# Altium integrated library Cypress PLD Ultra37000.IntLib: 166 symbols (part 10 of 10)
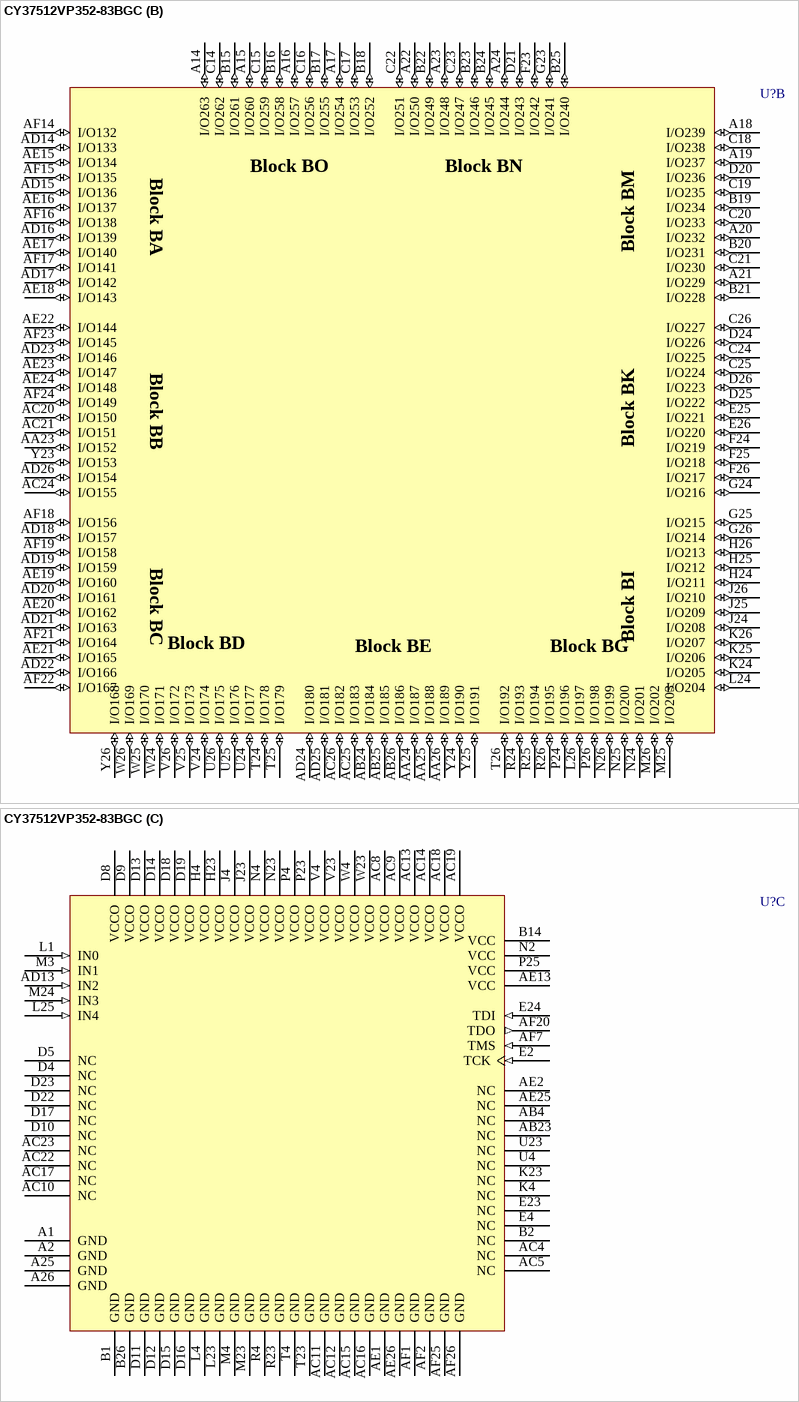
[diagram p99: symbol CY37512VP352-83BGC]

## CY37512VP352-83BGC
designator U?
Ultra37000 3.3V, ISR High-Performance CPLD
footprint BG352 (BGA, 388-Leads, Body 35x35mm, Pitch 1.27mm)
3D model CY37512VP352-BG352 (388-Ball Ball Grid Array 1.27 mm Pitch)
part A pins: A3 I/O19 (io), A4 I/O15 (io), A5 I/O13 (io), A6 I/O34 (io), A7 I/O31 (io), A8 I/O28 (io), A9 I/O25 (io), A10 I/O10 (io), A11 I/O7 (io), A12 I/O4 (io), A13 I/O1 (io), AA1 I/O74 (io), AA2 I/O75 (io), AA3 I/O76 (io), AA4 I/O111 (io), AB1 I/O77 (io), AB2 I/O78 (io), AB3 I/O79 (io), AC1 I/O81 (io), AC2 I/O80 (io), AC3 I/O108 (io), AC6 I/O112 (io), AC7 I/O113 (io), AD1 I/O109 (io), AD2 I/O82 (io), AD3 I/O83 (io), AD4 I/O117 (io), AD5 I/O97 (io), AD6 I/O100 (io), AD7 I/O102 (io), AD8 I/O105 (io), AD9 I/O120 (io), AD10 I/O123 (io), AD11 I/O126 (io), AD12 I/O129 (io), AE3 I/O115 (io), AE4 I/O116 (io), AE5 I/O119 (io), AE6 I/O98 (io), AE7 I/O101 (io), AE8 I/O103 (io), AE9 I/O106 (io), AE10 I/O121 (io), AE11 I/O124 (io), AE12 I/O127 (io), AE14 I/O130 (io), AF3 I/O114 (io), AF4 I/O118 (io), AF5 I/O96 (io), AF6 I/O99 (io), AF8 I/O104 (io), AF9 I/O107 (io), AF10 I/O122 (io), AF11 I/O125 (io), AF12 I/O128 (io), AF13 I/O131 (io), B3 I/O18 (io), B4 I/O17 (io), B5 I/O14 (io), B6 I/O35 (io), B7 I/O32 (io), B8 I/O29 (io), B9 I/O26 (io), B10 I/O11 (io), B11 I/O8 (io), B12 I/O5 (io), B13 I/O2 (io), C1 I/O23 (io), C2 I/O38 (io), C3 I/O37 (io), C4 I/O16 (io), C5 I/O12 (io), C6 I/O33 (io), C7 I/O30 (io), C8 I/O27 (io), C9 I/O24 (io), C10 I/O9 (io), C11 I/O6 (io), C12 I/O3 (io), C13 I/O0 (io), D1 I/O39 (io), D2 I/O40 (io), D3 I/O36 (io), D6 I/O21 (io), D7 I/O20 (io), E1 I/O42 (io), E3 I/O41 (io), F1 I/O45 (io), F2 I/O44 (io), F3 I/O43 (io), F4 I/O22 (io), G1 I/O48 (io), G2 I/O47 (io), G3 I/O46 (io), G4 I/O63 (io), H1 I/O49 (io), H2 I/O50 (io), H3 I/O51 (io), J1 I/O52 (io), J2 I/O53 (io), J3 I/O54 (io), K1 I/O55 (io), K2 I/O56 (io), K3 I/O57 (io), L2 I/O59 (io), L3 I/O58 (io), M1 I/O61 (io), M2 I/O60 (io), N1 I/O64 (io), N3 I/O62 (io), P1 I/O65 (io), P2 I/O66 (io), P3 I/O67 (io), R1 I/O68 (io), R2 I/O69 (io), R3 I/O70 (io), T1 I/O71 (io), T2 I/O84 (io), T3 I/O85 (io), U1 I/O88 (io), U2 I/O87 (io), U3 I/O86 (io), V1 I/O91 (io), V2 I/O90 (io), V3 I/O89 (io), W1 I/O94 (io), W2 I/O93 (io), W3 I/O92 (io), Y1 I/O95 (io), Y2 I/O72 (io), Y3 I/O73 (io), Y4 I/O110 (io)
part B pins: A14 I/O263 (io), A15 I/O260 (io), A16 I/O257 (io), A17 I/O254 (io), A18 I/O239 (io), A19 I/O237 (io), A20 I/O232 (io), A21 I/O229 (io), A22 I/O250 (io), A23 I/O248 (io), A24 I/O244 (io), AA23 I/O152 (io), AA24 I/O187 (io), AA25 I/O188 (io), AA26 I/O189 (io), AB24 I/O184 (io), AB25 I/O185 (io), AB26 I/O186 (io), AC20 I/O150 (io), AC21 I/O151 (io), AC24 I/O155 (io), AC25 I/O183 (io), AC26 I/O182 (io), AD14 I/O133 (io), AD15 I/O136 (io), AD16 I/O139 (io), AD17 I/O142 (io), AD18 I/O157 (io), AD19 I/O159 (io), AD20 I/O161 (io), AD21 I/O163 (io), AD22 I/O166 (io), AD23 I/O146 (io), AD24 I/O180 (io), AD25 I/O181 (io), AD26 I/O154 (io), AE15 I/O134 (io), AE16 I/O137 (io), AE17 I/O140 (io), AE18 I/O143 (io), AE19 I/O160 (io), AE20 I/O162 (io), AE21 I/O165 (io), AE22 I/O144 (io), AE23 I/O147 (io), AE24 I/O148 (io), AF14 I/O132 (io), AF15 I/O135 (io), AF16 I/O138 (io), AF17 I/O141 (io), AF18 I/O156 (io), AF19 I/O158 (io), AF21 I/O164 (io), AF22 I/O167 (io), AF23 I/O145 (io), AF24 I/O149 (io), B15 I/O261 (io), B16 I/O258 (io), B17 I/O255 (io), B18 I/O252 (io), B19 I/O234 (io), B20 I/O231 (io), B21 I/O228 (io), B22 I/O249 (io), B23 I/O246 (io), B24 I/O245 (io), B25 I/O240 (io), C14 I/O262 (io), C15 I/O259 (io), C16 I/O256 (io), C17 I/O253 (io), C18 I/O238 (io), C19 I/O235 (io), C20 I/O233 (io), C21 I/O230 (io), C22 I/O251 (io), C23 I/O247 (io), C24 I/O225 (io), C25 I/O224 (io), C26 I/O227 (io), D20 I/O236 (io), D21 I/O243 (io), D24 I/O226 (io), D25 I/O222 (io), D26 I/O223 (io), E25 I/O221 (io), E26 I/O220 (io), F23 I/O242 (io), F24 I/O219 (io), F25 I/O218 (io), F26 I/O217 (io), G23 I/O241 (io), G24 I/O216 (io), G25 I/O215 (io), G26 I/O214 (io), H24 I/O211 (io), H25 I/O212 (io), H26 I/O213 (io), J24 I/O208 (io), J25 I/O209 (io), J26 I/O210 (io), K24 I/O205 (io), K25 I/O206 (io), K26 I/O207 (io), L24 I/O204 (io), L26 I/O197 (io), M25 I/O203 (io), M26 I/O202 (io), N24 I/O201 (io), N25 I/O200 (io), N26 I/O199 (io), P24 I/O196 (io), P26 I/O198 (io), R24 I/O193 (io), R25 I/O194 (io), R26 I/O195 (io), T24 I/O178 (io), T25 I/O179 (io), T26 I/O192 (io), U24 I/O177 (io), U25 I/O176 (io), U26 I/O175 (io), V24 I/O174 (io), V25 I/O173 (io), V26 I/O172 (io), W24 I/O171 (io), W25 I/O170 (io), W26 I/O169 (io), Y23 I/O153 (io), Y24 I/O190 (io), Y25 I/O191 (io), Y26 I/O168 (io)
part C pins: A1 GND (power), A2 GND (power), A25 GND (power), A26 GND (power), AB4 NC, AB23 NC, AC4 NC, AC5 NC, AC8 VCCO (power), AC9 VCCO (power), AC10 NC, AC11 GND (power), AC12 GND (power), AC13 VCCO (power), AC14 VCCO (power), AC15 GND (power), AC16 GND (power), AC17 NC, AC18 VCCO (power), AC19 VCCO (power), AC22 NC, AC23 NC, AD13 IN2 (in), AE1 GND (power), AE2 NC, AE13 VCC (power), AE25 NC, AE26 GND (power), AF1 GND (power), AF2 GND (power), AF7 TMS (in), AF20 TDO (out), AF25 GND (power), AF26 GND (power), B1 GND (power), B2 NC, B14 VCC (power), B26 GND (power), D4 NC, D5 NC, D8 VCCO (power), D9 VCCO (power), D10 NC, D11 GND (power), D12 GND (power), D13 VCCO (power), D14 VCCO (power), D15 GND (power), D16 GND (power), D17 NC, D18 VCCO (power), D19 VCCO (power), D22 NC, D23 NC, E2 TCK (in), E4 NC, E23 NC, E24 TDI (in), H4 VCCO (power), H23 VCCO (power), J4 VCCO (power), J23 VCCO (power), K4 NC, K23 NC, L1 IN0 (in), L4 GND (power), L23 GND (power), L25 IN4 (in), M3 IN1 (in), M4 GND (power), M23 GND (power), M24 IN3 (in), N2 VCC (power), N4 VCCO (power), N23 VCCO (power), P4 VCCO (power), P23 VCCO (power), P25 VCC (power), R4 GND (power), R23 GND (power), T4 GND (power), T23 GND (power), U4 NC, U23 NC, V4 VCCO (power), V23 VCCO (power), W4 VCCO (power), W23 VCCO (power)

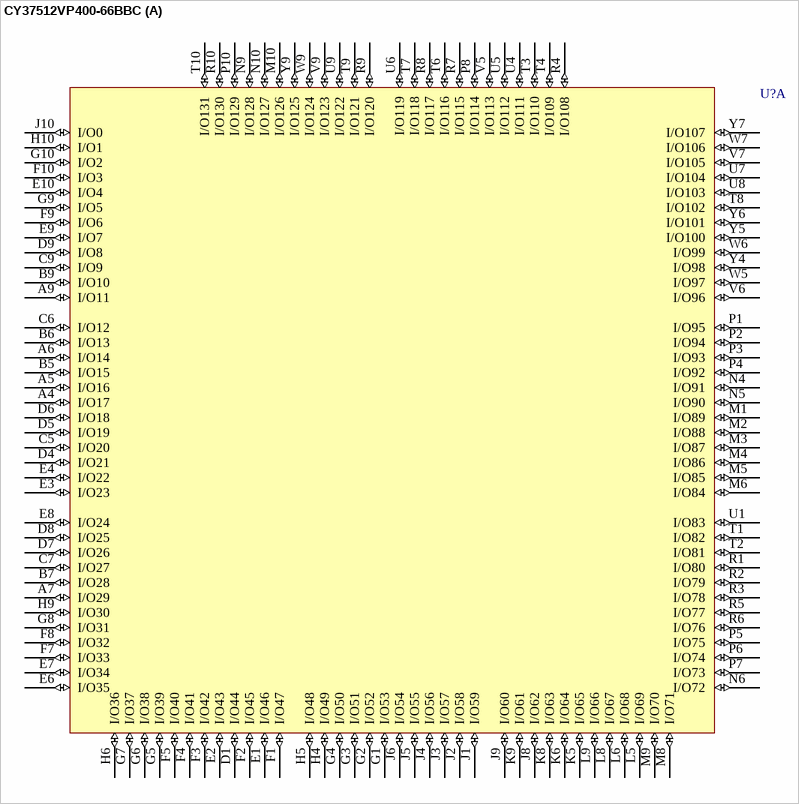
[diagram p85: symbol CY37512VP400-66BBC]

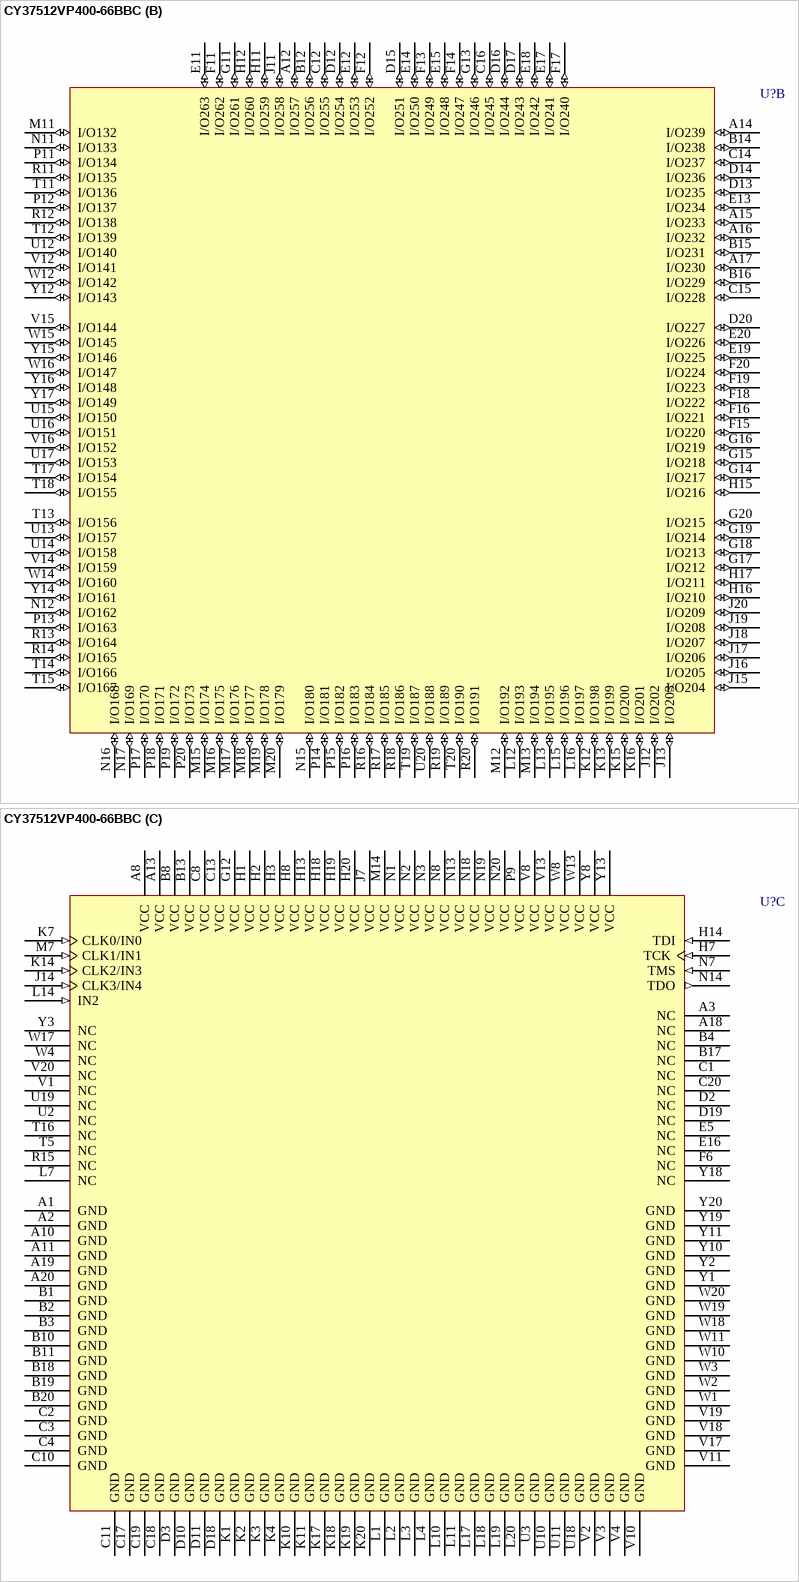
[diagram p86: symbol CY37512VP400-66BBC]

## CY37512VP400-66BBC
designator U?
Ultra37000 3.3V, ISR High-Performance CPLD
footprint BB400 (BGA, 400-Leads, Body 21x21mm, Pitch 1mm)
3D model CY37512VP400-BB400 (400-Ball Fine Pitch Ball Grid Array 1 mm Pitch)
part A pins: A4 I/O17 (io), A5 I/O16 (io), A6 I/O14 (io), A7 I/O29 (io), A9 I/O11 (io), B5 I/O15 (io), B6 I/O13 (io), B7 I/O28 (io), B9 I/O10 (io), C5 I/O20 (io), C6 I/O12 (io), C7 I/O27 (io), C9 I/O9 (io), D1 I/O44 (io), D4 I/O21 (io), D5 I/O19 (io), D6 I/O18 (io), D7 I/O26 (io), D8 I/O25 (io), D9 I/O8 (io), E1 I/O46 (io), E2 I/O43 (io), E3 I/O23 (io), E4 I/O22 (io), E6 I/O35 (io), E7 I/O34 (io), E8 I/O24 (io), E9 I/O7 (io), E10 I/O4 (io), F1 I/O47 (io), F2 I/O45 (io), F3 I/O42 (io), F4 I/O41 (io), F5 I/O40 (io), F7 I/O33 (io), F8 I/O32 (io), F9 I/O6 (io), F10 I/O3 (io), G1 I/O53 (io), G2 I/O52 (io), G3 I/O51 (io), G4 I/O50 (io), G5 I/O39 (io), G6 I/O38 (io), G7 I/O37 (io), G8 I/O31 (io), G9 I/O5 (io), G10 I/O2 (io), H4 I/O49 (io), H5 I/O48 (io), H6 I/O36 (io), H9 I/O30 (io), H10 I/O1 (io), J1 I/O59 (io), J2 I/O58 (io), J3 I/O57 (io), J4 I/O56 (io), J5 I/O55 (io), J6 I/O54 (io), J8 I/O62 (io), J9 I/O60 (io), J10 I/O0 (io), K5 I/O65 (io), K6 I/O64 (io), K8 I/O63 (io), K9 I/O61 (io), L5 I/O69 (io), L6 I/O68 (io), L8 I/O67 (io), L9 I/O66 (io), M1 I/O89 (io), M2 I/O88 (io), M3 I/O87 (io), M4 I/O86 (io), M5 I/O85 (io), M6 I/O84 (io), M8 I/O71 (io), M9 I/O70 (io), M10 I/O126 (io), N4 I/O91 (io), N5 I/O90 (io), N6 I/O72 (io), N9 I/O128 (io), N10 I/O127 (io), P1 I/O95 (io), P2 I/O94 (io), P3 I/O93 (io), P4 I/O92 (io), P5 I/O75 (io), P6 I/O74 (io), P7 I/O73 (io), P8 I/O114 (io), P10 I/O129 (io), R1 I/O80 (io), R2 I/O79 (io), R3 I/O78 (io), R4 I/O108 (io), R5 I/O77 (io), R6 I/O76 (io), R7 I/O115 (io), R8 I/O117 (io), R9 I/O120 (io), R10 I/O130 (io), T1 I/O82 (io), T2 I/O81 (io), T3 I/O110 (io), T4 I/O109 (io), T6 I/O116 (io), T7 I/O118 (io), T8 I/O102 (io), T9 I/O121 (io), T10 I/O131 (io), U1 I/O83 (io), U4 I/O111 (io), U5 I/O112 (io), U6 I/O119 (io), U7 I/O104 (io), U8 I/O103 (io), U9 I/O122 (io), V5 I/O113 (io), V6 I/O96 (io), V7 I/O105 (io), V9 I/O123 (io), W5 I/O97 (io), W6 I/O99 (io), W7 I/O106 (io), W9 I/O124 (io), Y4 I/O98 (io), Y5 I/O100 (io), Y6 I/O101 (io), Y7 I/O107 (io), Y9 I/O125 (io)
part B pins: A12 I/O257 (io), A14 I/O239 (io), A15 I/O233 (io), A16 I/O232 (io), A17 I/O230 (io), B12 I/O256 (io), B14 I/O238 (io), B15 I/O231 (io), B16 I/O229 (io), C12 I/O255 (io), C14 I/O237 (io), C15 I/O228 (io), C16 I/O245 (io), D12 I/O254 (io), D13 I/O235 (io), D14 I/O236 (io), D15 I/O251 (io), D16 I/O244 (io), D17 I/O243 (io), D20 I/O227 (io), E11 I/O263 (io), E12 I/O253 (io), E13 I/O234 (io), E14 I/O250 (io), E15 I/O248 (io), E17 I/O241 (io), E18 I/O242 (io), E19 I/O225 (io), E20 I/O226 (io), F11 I/O262 (io), F12 I/O252 (io), F13 I/O249 (io), F14 I/O247 (io), F15 I/O220 (io), F16 I/O221 (io), F17 I/O240 (io), F18 I/O222 (io), F19 I/O223 (io), F20 I/O224 (io), G11 I/O261 (io), G13 I/O246 (io), G14 I/O217 (io), G15 I/O218 (io), G16 I/O219 (io), G17 I/O212 (io), G18 I/O213 (io), G19 I/O214 (io), G20 I/O215 (io), H11 I/O259 (io), H12 I/O260 (io), H15 I/O216 (io), H16 I/O210 (io), H17 I/O211 (io), J11 I/O258 (io), J12 I/O202 (io), J13 I/O203 (io), J15 I/O204 (io), J16 I/O205 (io), J17 I/O206 (io), J18 I/O207 (io), J19 I/O208 (io), J20 I/O209 (io), K12 I/O198 (io), K13 I/O199 (io), K15 I/O200 (io), K16 I/O201 (io), L12 I/O193 (io), L13 I/O195 (io), L15 I/O196 (io), L16 I/O197 (io), M11 I/O132 (io), M12 I/O192 (io), M13 I/O194 (io), M15 I/O174 (io), M16 I/O175 (io), M17 I/O176 (io), M18 I/O177 (io), M19 I/O178 (io), M20 I/O179 (io), N11 I/O133 (io), N12 I/O162 (io), N15 I/O180 (io), N16 I/O168 (io), N17 I/O169 (io), P11 I/O134 (io), P12 I/O137 (io), P13 I/O163 (io), P14 I/O181 (io), P15 I/O182 (io), P16 I/O183 (io), P17 I/O170 (io), P18 I/O171 (io), P19 I/O172 (io), P20 I/O173 (io), R11 I/O135 (io), R12 I/O138 (io), R13 I/O164 (io), R14 I/O165 (io), R16 I/O184 (io), R17 I/O185 (io), R18 I/O186 (io), R19 I/O189 (io), R20 I/O191 (io), T11 I/O136 (io), T12 I/O139 (io), T13 I/O156 (io), T14 I/O166 (io), T15 I/O167 (io), T17 I/O154 (io), T18 I/O155 (io), T19 I/O187 (io), T20 I/O190 (io), U12 I/O140 (io), U13 I/O157 (io), U14 I/O158 (io), U15 I/O150 (io), U16 I/O151 (io), U17 I/O153 (io), U20 I/O188 (io), V12 I/O141 (io), V14 I/O159 (io), V15 I/O144 (io), V16 I/O152 (io), W12 I/O142 (io), W14 I/O160 (io), W15 I/O145 (io), W16 I/O147 (io), Y12 I/O143 (io), Y14 I/O161 (io), Y15 I/O146 (io), Y16 I/O148 (io), Y17 I/O149 (io)
part C pins: A1 GND (power), A2 GND (power), A3 NC, A8 VCC (power), A10 GND (power), A11 GND (power), A13 VCC (power), A18 NC, A19 GND (power), A20 GND (power), B1 GND (power), B2 GND (power), B3 GND (power), B4 NC, B8 VCC (power), B10 GND (power), B11 GND (power), B13 VCC (power), B17 NC, B18 GND (power), B19 GND (power), B20 GND (power), C1 NC, C2 GND (power), C3 GND (power), C4 GND (power), C8 VCC (power), C10 GND (power), C11 GND (power), C13 VCC (power), C17 GND (power), C18 GND (power), C19 GND (power), C20 NC, D2 NC, D3 GND (power), D10 GND (power), D11 GND (power), D18 GND (power), D19 NC, E5 NC, E16 NC, F6 NC, G12 VCC (power), H1 VCC (power), H2 VCC (power), H3 VCC (power), H7 TCK (in), H8 VCC (power), H13 VCC (power), H14 TDI (in), H18 VCC (power), H19 VCC (power), H20 VCC (power), J7 VCC (power), J14 CLK3/IN4 (in), K1 GND (power), K2 GND (power), K3 GND (power), K4 GND (power), K7 CLK0/IN0 (in), K10 GND (power), K11 GND (power), K14 CLK2/IN3 (in), K17 GND (power), K18 GND (power), K19 GND (power), K20 GND (power), L1 GND (power), L2 GND (power), L3 GND (power), L4 GND (power), L7 NC, L10 GND (power), L11 GND (power), L14 IN2 (in), L17 GND (power), L18 GND (power), L19 GND (power), L20 GND (power), M7 CLK1/IN1 (in), M14 VCC (power), N1 VCC (power), N2 VCC (power), N3 VCC (power), N7 TMS (in), N8 VCC (power), N13 VCC (power), N14 TDO (out), N18 VCC (power), N19 VCC (power), N20 VCC (power), P9 VCC (power), R15 NC, T5 NC, T16 NC, U2 NC, U3 GND (power), U10 GND (power), U11 GND (power), U18 GND (power), U19 NC, V1 NC, V2 GND (power), V3 GND (power), V4 GND (power), V8 VCC (power), V10 GND (power), V11 GND (power), V13 VCC (power), V17 GND (power), V18 GND (power), V19 GND (power), V20 NC, W1 GND (power), W2 GND (power), W3 GND (power), W4 NC, W8 VCC (power), W10 GND (power), W11 GND (power), W13 VCC (power), W17 NC, W18 GND (power), W19 GND (power), W20 GND (power), Y1 GND (power), Y2 GND (power), Y3 NC, Y8 VCC (power), Y10 GND (power), Y11 GND (power), Y13 VCC (power), Y18 NC, Y19 GND (power), Y20 GND (power)

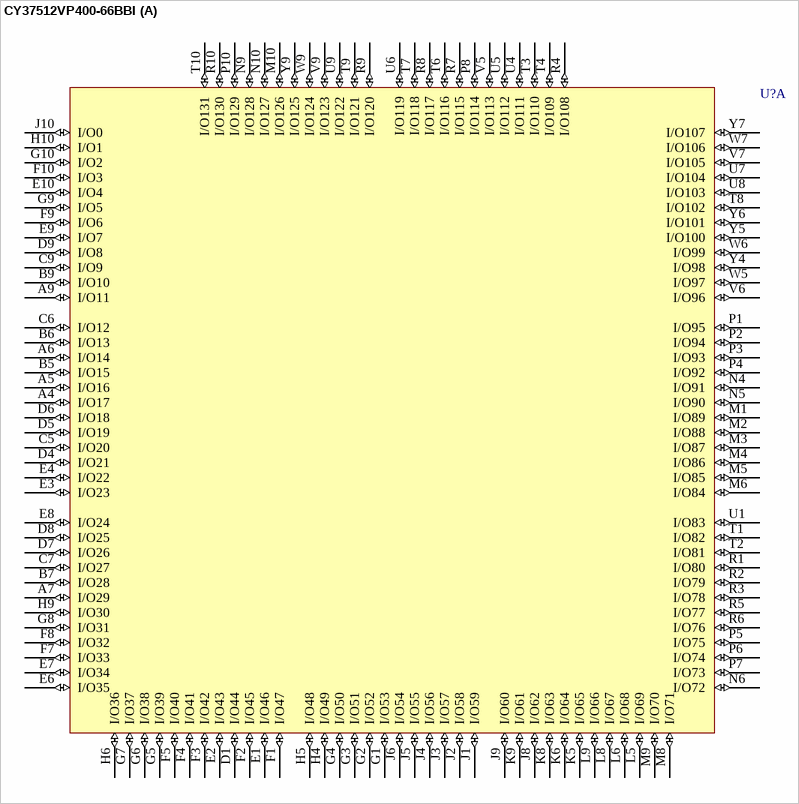
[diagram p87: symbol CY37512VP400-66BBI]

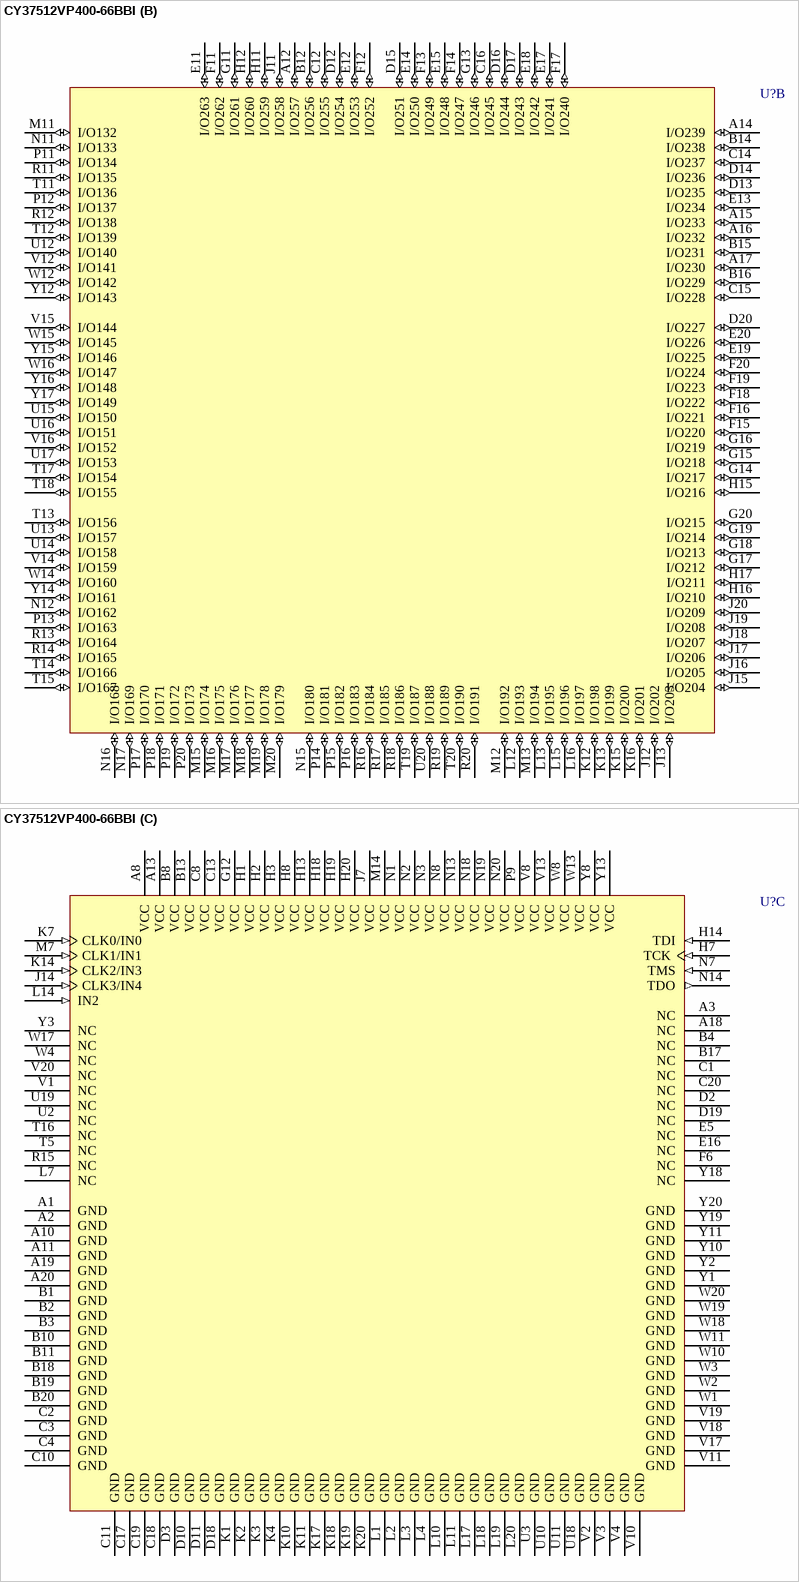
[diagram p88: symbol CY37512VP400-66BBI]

## CY37512VP400-66BBI
designator U?
Ultra37000 3.3V, ISR High-Performance CPLD
footprint BB400 (BGA, 400-Leads, Body 21x21mm, Pitch 1mm)
3D model CY37512VP400-BB400 (400-Ball Fine Pitch Ball Grid Array 1 mm Pitch)
part A pins: A4 I/O17 (io), A5 I/O16 (io), A6 I/O14 (io), A7 I/O29 (io), A9 I/O11 (io), B5 I/O15 (io), B6 I/O13 (io), B7 I/O28 (io), B9 I/O10 (io), C5 I/O20 (io), C6 I/O12 (io), C7 I/O27 (io), C9 I/O9 (io), D1 I/O44 (io), D4 I/O21 (io), D5 I/O19 (io), D6 I/O18 (io), D7 I/O26 (io), D8 I/O25 (io), D9 I/O8 (io), E1 I/O46 (io), E2 I/O43 (io), E3 I/O23 (io), E4 I/O22 (io), E6 I/O35 (io), E7 I/O34 (io), E8 I/O24 (io), E9 I/O7 (io), E10 I/O4 (io), F1 I/O47 (io), F2 I/O45 (io), F3 I/O42 (io), F4 I/O41 (io), F5 I/O40 (io), F7 I/O33 (io), F8 I/O32 (io), F9 I/O6 (io), F10 I/O3 (io), G1 I/O53 (io), G2 I/O52 (io), G3 I/O51 (io), G4 I/O50 (io), G5 I/O39 (io), G6 I/O38 (io), G7 I/O37 (io), G8 I/O31 (io), G9 I/O5 (io), G10 I/O2 (io), H4 I/O49 (io), H5 I/O48 (io), H6 I/O36 (io), H9 I/O30 (io), H10 I/O1 (io), J1 I/O59 (io), J2 I/O58 (io), J3 I/O57 (io), J4 I/O56 (io), J5 I/O55 (io), J6 I/O54 (io), J8 I/O62 (io), J9 I/O60 (io), J10 I/O0 (io), K5 I/O65 (io), K6 I/O64 (io), K8 I/O63 (io), K9 I/O61 (io), L5 I/O69 (io), L6 I/O68 (io), L8 I/O67 (io), L9 I/O66 (io), M1 I/O89 (io), M2 I/O88 (io), M3 I/O87 (io), M4 I/O86 (io), M5 I/O85 (io), M6 I/O84 (io), M8 I/O71 (io), M9 I/O70 (io), M10 I/O126 (io), N4 I/O91 (io), N5 I/O90 (io), N6 I/O72 (io), N9 I/O128 (io), N10 I/O127 (io), P1 I/O95 (io), P2 I/O94 (io), P3 I/O93 (io), P4 I/O92 (io), P5 I/O75 (io), P6 I/O74 (io), P7 I/O73 (io), P8 I/O114 (io), P10 I/O129 (io), R1 I/O80 (io), R2 I/O79 (io), R3 I/O78 (io), R4 I/O108 (io), R5 I/O77 (io), R6 I/O76 (io), R7 I/O115 (io), R8 I/O117 (io), R9 I/O120 (io), R10 I/O130 (io), T1 I/O82 (io), T2 I/O81 (io), T3 I/O110 (io), T4 I/O109 (io), T6 I/O116 (io), T7 I/O118 (io), T8 I/O102 (io), T9 I/O121 (io), T10 I/O131 (io), U1 I/O83 (io), U4 I/O111 (io), U5 I/O112 (io), U6 I/O119 (io), U7 I/O104 (io), U8 I/O103 (io), U9 I/O122 (io), V5 I/O113 (io), V6 I/O96 (io), V7 I/O105 (io), V9 I/O123 (io), W5 I/O97 (io), W6 I/O99 (io), W7 I/O106 (io), W9 I/O124 (io), Y4 I/O98 (io), Y5 I/O100 (io), Y6 I/O101 (io), Y7 I/O107 (io), Y9 I/O125 (io)
part B pins: A12 I/O257 (io), A14 I/O239 (io), A15 I/O233 (io), A16 I/O232 (io), A17 I/O230 (io), B12 I/O256 (io), B14 I/O238 (io), B15 I/O231 (io), B16 I/O229 (io), C12 I/O255 (io), C14 I/O237 (io), C15 I/O228 (io), C16 I/O245 (io), D12 I/O254 (io), D13 I/O235 (io), D14 I/O236 (io), D15 I/O251 (io), D16 I/O244 (io), D17 I/O243 (io), D20 I/O227 (io), E11 I/O263 (io), E12 I/O253 (io), E13 I/O234 (io), E14 I/O250 (io), E15 I/O248 (io), E17 I/O241 (io), E18 I/O242 (io), E19 I/O225 (io), E20 I/O226 (io), F11 I/O262 (io), F12 I/O252 (io), F13 I/O249 (io), F14 I/O247 (io), F15 I/O220 (io), F16 I/O221 (io), F17 I/O240 (io), F18 I/O222 (io), F19 I/O223 (io), F20 I/O224 (io), G11 I/O261 (io), G13 I/O246 (io), G14 I/O217 (io), G15 I/O218 (io), G16 I/O219 (io), G17 I/O212 (io), G18 I/O213 (io), G19 I/O214 (io), G20 I/O215 (io), H11 I/O259 (io), H12 I/O260 (io), H15 I/O216 (io), H16 I/O210 (io), H17 I/O211 (io), J11 I/O258 (io), J12 I/O202 (io), J13 I/O203 (io), J15 I/O204 (io), J16 I/O205 (io), J17 I/O206 (io), J18 I/O207 (io), J19 I/O208 (io), J20 I/O209 (io), K12 I/O198 (io), K13 I/O199 (io), K15 I/O200 (io), K16 I/O201 (io), L12 I/O193 (io), L13 I/O195 (io), L15 I/O196 (io), L16 I/O197 (io), M11 I/O132 (io), M12 I/O192 (io), M13 I/O194 (io), M15 I/O174 (io), M16 I/O175 (io), M17 I/O176 (io), M18 I/O177 (io), M19 I/O178 (io), M20 I/O179 (io), N11 I/O133 (io), N12 I/O162 (io), N15 I/O180 (io), N16 I/O168 (io), N17 I/O169 (io), P11 I/O134 (io), P12 I/O137 (io), P13 I/O163 (io), P14 I/O181 (io), P15 I/O182 (io), P16 I/O183 (io), P17 I/O170 (io), P18 I/O171 (io), P19 I/O172 (io), P20 I/O173 (io), R11 I/O135 (io), R12 I/O138 (io), R13 I/O164 (io), R14 I/O165 (io), R16 I/O184 (io), R17 I/O185 (io), R18 I/O186 (io), R19 I/O189 (io), R20 I/O191 (io), T11 I/O136 (io), T12 I/O139 (io), T13 I/O156 (io), T14 I/O166 (io), T15 I/O167 (io), T17 I/O154 (io), T18 I/O155 (io), T19 I/O187 (io), T20 I/O190 (io), U12 I/O140 (io), U13 I/O157 (io), U14 I/O158 (io), U15 I/O150 (io), U16 I/O151 (io), U17 I/O153 (io), U20 I/O188 (io), V12 I/O141 (io), V14 I/O159 (io), V15 I/O144 (io), V16 I/O152 (io), W12 I/O142 (io), W14 I/O160 (io), W15 I/O145 (io), W16 I/O147 (io), Y12 I/O143 (io), Y14 I/O161 (io), Y15 I/O146 (io), Y16 I/O148 (io), Y17 I/O149 (io)
part C pins: A1 GND (power), A2 GND (power), A3 NC, A8 VCC (power), A10 GND (power), A11 GND (power), A13 VCC (power), A18 NC, A19 GND (power), A20 GND (power), B1 GND (power), B2 GND (power), B3 GND (power), B4 NC, B8 VCC (power), B10 GND (power), B11 GND (power), B13 VCC (power), B17 NC, B18 GND (power), B19 GND (power), B20 GND (power), C1 NC, C2 GND (power), C3 GND (power), C4 GND (power), C8 VCC (power), C10 GND (power), C11 GND (power), C13 VCC (power), C17 GND (power), C18 GND (power), C19 GND (power), C20 NC, D2 NC, D3 GND (power), D10 GND (power), D11 GND (power), D18 GND (power), D19 NC, E5 NC, E16 NC, F6 NC, G12 VCC (power), H1 VCC (power), H2 VCC (power), H3 VCC (power), H7 TCK (in), H8 VCC (power), H13 VCC (power), H14 TDI (in), H18 VCC (power), H19 VCC (power), H20 VCC (power), J7 VCC (power), J14 CLK3/IN4 (in), K1 GND (power), K2 GND (power), K3 GND (power), K4 GND (power), K7 CLK0/IN0 (in), K10 GND (power), K11 GND (power), K14 CLK2/IN3 (in), K17 GND (power), K18 GND (power), K19 GND (power), K20 GND (power), L1 GND (power), L2 GND (power), L3 GND (power), L4 GND (power), L7 NC, L10 GND (power), L11 GND (power), L14 IN2 (in), L17 GND (power), L18 GND (power), L19 GND (power), L20 GND (power), M7 CLK1/IN1 (in), M14 VCC (power), N1 VCC (power), N2 VCC (power), N3 VCC (power), N7 TMS (in), N8 VCC (power), N13 VCC (power), N14 TDO (out), N18 VCC (power), N19 VCC (power), N20 VCC (power), P9 VCC (power), R15 NC, T5 NC, T16 NC, U2 NC, U3 GND (power), U10 GND (power), U11 GND (power), U18 GND (power), U19 NC, V1 NC, V2 GND (power), V3 GND (power), V4 GND (power), V8 VCC (power), V10 GND (power), V11 GND (power), V13 VCC (power), V17 GND (power), V18 GND (power), V19 GND (power), V20 NC, W1 GND (power), W2 GND (power), W3 GND (power), W4 NC, W8 VCC (power), W10 GND (power), W11 GND (power), W13 VCC (power), W17 NC, W18 GND (power), W19 GND (power), W20 GND (power), Y1 GND (power), Y2 GND (power), Y3 NC, Y8 VCC (power), Y10 GND (power), Y11 GND (power), Y13 VCC (power), Y18 NC, Y19 GND (power), Y20 GND (power)

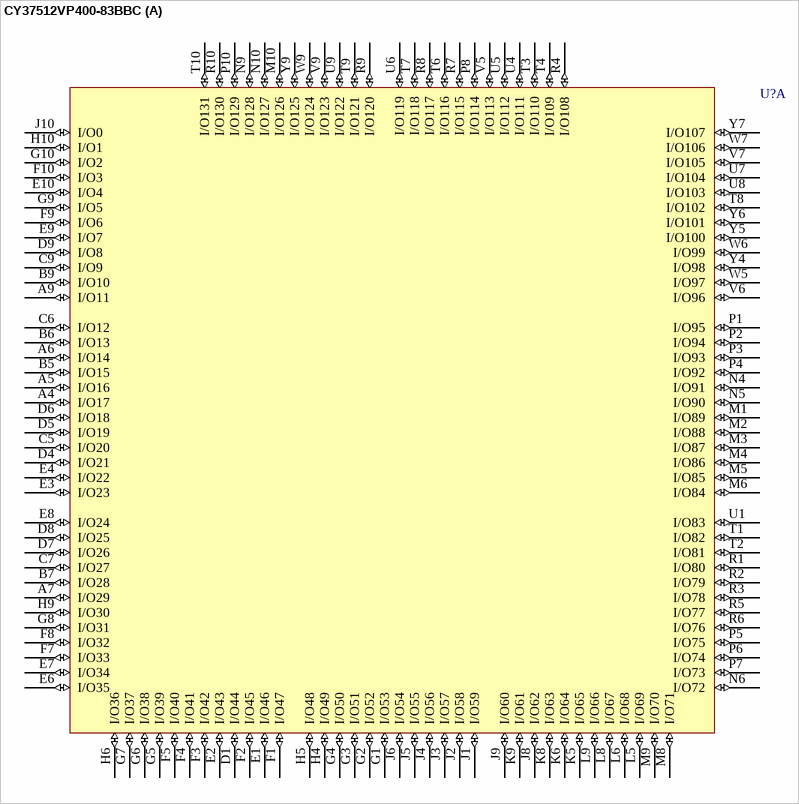
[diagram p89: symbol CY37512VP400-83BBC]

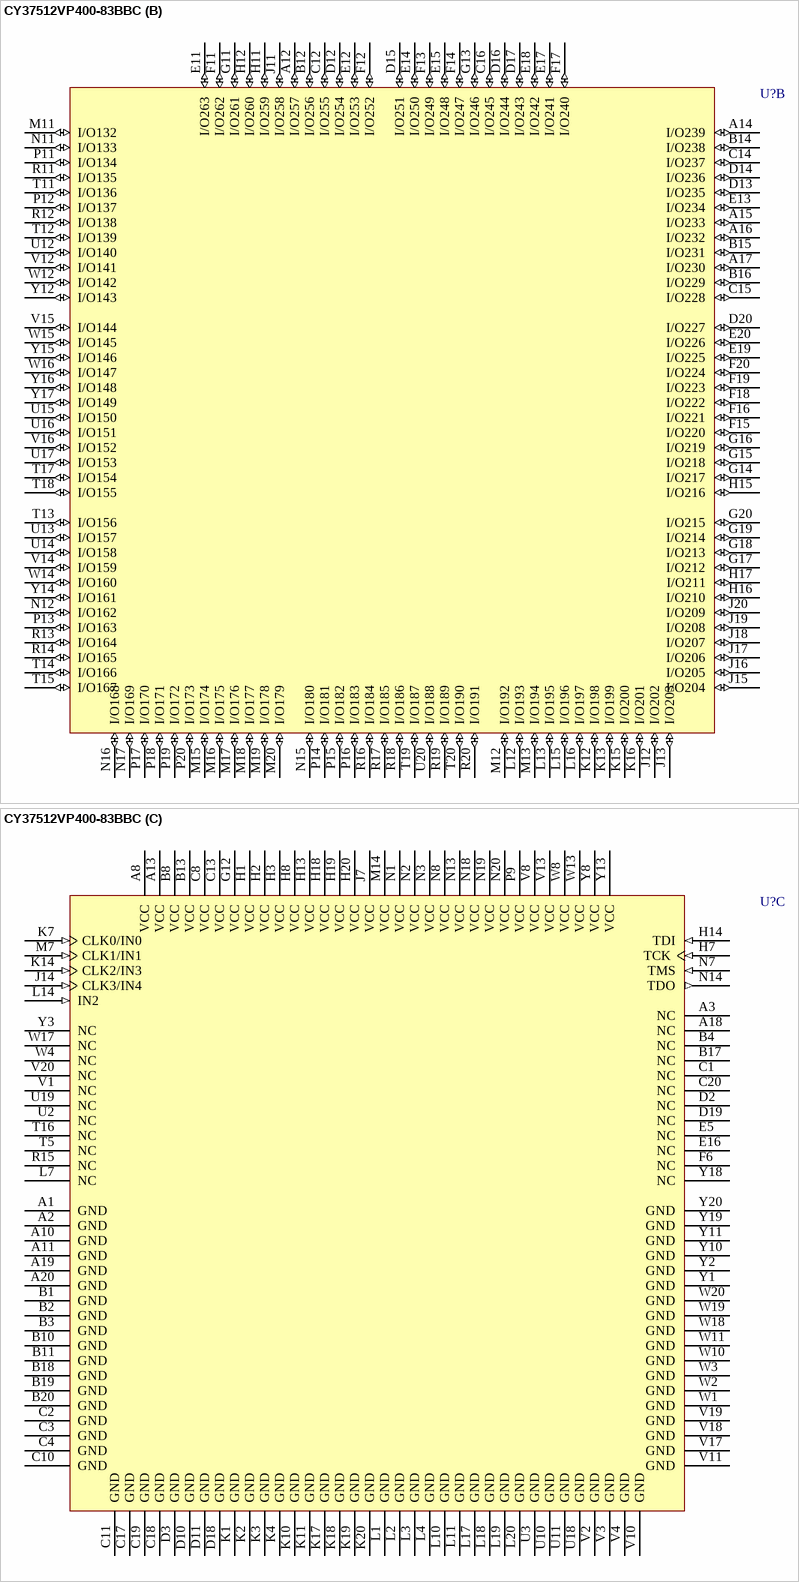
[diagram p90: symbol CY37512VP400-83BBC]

## CY37512VP400-83BBC
designator U?
Ultra37000 3.3V, ISR High-Performance CPLD
footprint BB400 (BGA, 400-Leads, Body 21x21mm, Pitch 1mm)
3D model CY37512VP400-BB400 (400-Ball Fine Pitch Ball Grid Array 1 mm Pitch)
part A pins: A4 I/O17 (io), A5 I/O16 (io), A6 I/O14 (io), A7 I/O29 (io), A9 I/O11 (io), B5 I/O15 (io), B6 I/O13 (io), B7 I/O28 (io), B9 I/O10 (io), C5 I/O20 (io), C6 I/O12 (io), C7 I/O27 (io), C9 I/O9 (io), D1 I/O44 (io), D4 I/O21 (io), D5 I/O19 (io), D6 I/O18 (io), D7 I/O26 (io), D8 I/O25 (io), D9 I/O8 (io), E1 I/O46 (io), E2 I/O43 (io), E3 I/O23 (io), E4 I/O22 (io), E6 I/O35 (io), E7 I/O34 (io), E8 I/O24 (io), E9 I/O7 (io), E10 I/O4 (io), F1 I/O47 (io), F2 I/O45 (io), F3 I/O42 (io), F4 I/O41 (io), F5 I/O40 (io), F7 I/O33 (io), F8 I/O32 (io), F9 I/O6 (io), F10 I/O3 (io), G1 I/O53 (io), G2 I/O52 (io), G3 I/O51 (io), G4 I/O50 (io), G5 I/O39 (io), G6 I/O38 (io), G7 I/O37 (io), G8 I/O31 (io), G9 I/O5 (io), G10 I/O2 (io), H4 I/O49 (io), H5 I/O48 (io), H6 I/O36 (io), H9 I/O30 (io), H10 I/O1 (io), J1 I/O59 (io), J2 I/O58 (io), J3 I/O57 (io), J4 I/O56 (io), J5 I/O55 (io), J6 I/O54 (io), J8 I/O62 (io), J9 I/O60 (io), J10 I/O0 (io), K5 I/O65 (io), K6 I/O64 (io), K8 I/O63 (io), K9 I/O61 (io), L5 I/O69 (io), L6 I/O68 (io), L8 I/O67 (io), L9 I/O66 (io), M1 I/O89 (io), M2 I/O88 (io), M3 I/O87 (io), M4 I/O86 (io), M5 I/O85 (io), M6 I/O84 (io), M8 I/O71 (io), M9 I/O70 (io), M10 I/O126 (io), N4 I/O91 (io), N5 I/O90 (io), N6 I/O72 (io), N9 I/O128 (io), N10 I/O127 (io), P1 I/O95 (io), P2 I/O94 (io), P3 I/O93 (io), P4 I/O92 (io), P5 I/O75 (io), P6 I/O74 (io), P7 I/O73 (io), P8 I/O114 (io), P10 I/O129 (io), R1 I/O80 (io), R2 I/O79 (io), R3 I/O78 (io), R4 I/O108 (io), R5 I/O77 (io), R6 I/O76 (io), R7 I/O115 (io), R8 I/O117 (io), R9 I/O120 (io), R10 I/O130 (io), T1 I/O82 (io), T2 I/O81 (io), T3 I/O110 (io), T4 I/O109 (io), T6 I/O116 (io), T7 I/O118 (io), T8 I/O102 (io), T9 I/O121 (io), T10 I/O131 (io), U1 I/O83 (io), U4 I/O111 (io), U5 I/O112 (io), U6 I/O119 (io), U7 I/O104 (io), U8 I/O103 (io), U9 I/O122 (io), V5 I/O113 (io), V6 I/O96 (io), V7 I/O105 (io), V9 I/O123 (io), W5 I/O97 (io), W6 I/O99 (io), W7 I/O106 (io), W9 I/O124 (io), Y4 I/O98 (io), Y5 I/O100 (io), Y6 I/O101 (io), Y7 I/O107 (io), Y9 I/O125 (io)
part B pins: A12 I/O257 (io), A14 I/O239 (io), A15 I/O233 (io), A16 I/O232 (io), A17 I/O230 (io), B12 I/O256 (io), B14 I/O238 (io), B15 I/O231 (io), B16 I/O229 (io), C12 I/O255 (io), C14 I/O237 (io), C15 I/O228 (io), C16 I/O245 (io), D12 I/O254 (io), D13 I/O235 (io), D14 I/O236 (io), D15 I/O251 (io), D16 I/O244 (io), D17 I/O243 (io), D20 I/O227 (io), E11 I/O263 (io), E12 I/O253 (io), E13 I/O234 (io), E14 I/O250 (io), E15 I/O248 (io), E17 I/O241 (io), E18 I/O242 (io), E19 I/O225 (io), E20 I/O226 (io), F11 I/O262 (io), F12 I/O252 (io), F13 I/O249 (io), F14 I/O247 (io), F15 I/O220 (io), F16 I/O221 (io), F17 I/O240 (io), F18 I/O222 (io), F19 I/O223 (io), F20 I/O224 (io), G11 I/O261 (io), G13 I/O246 (io), G14 I/O217 (io), G15 I/O218 (io), G16 I/O219 (io), G17 I/O212 (io), G18 I/O213 (io), G19 I/O214 (io), G20 I/O215 (io), H11 I/O259 (io), H12 I/O260 (io), H15 I/O216 (io), H16 I/O210 (io), H17 I/O211 (io), J11 I/O258 (io), J12 I/O202 (io), J13 I/O203 (io), J15 I/O204 (io), J16 I/O205 (io), J17 I/O206 (io), J18 I/O207 (io), J19 I/O208 (io), J20 I/O209 (io), K12 I/O198 (io), K13 I/O199 (io), K15 I/O200 (io), K16 I/O201 (io), L12 I/O193 (io), L13 I/O195 (io), L15 I/O196 (io), L16 I/O197 (io), M11 I/O132 (io), M12 I/O192 (io), M13 I/O194 (io), M15 I/O174 (io), M16 I/O175 (io), M17 I/O176 (io), M18 I/O177 (io), M19 I/O178 (io), M20 I/O179 (io), N11 I/O133 (io), N12 I/O162 (io), N15 I/O180 (io), N16 I/O168 (io), N17 I/O169 (io), P11 I/O134 (io), P12 I/O137 (io), P13 I/O163 (io), P14 I/O181 (io), P15 I/O182 (io), P16 I/O183 (io), P17 I/O170 (io), P18 I/O171 (io), P19 I/O172 (io), P20 I/O173 (io), R11 I/O135 (io), R12 I/O138 (io), R13 I/O164 (io), R14 I/O165 (io), R16 I/O184 (io), R17 I/O185 (io), R18 I/O186 (io), R19 I/O189 (io), R20 I/O191 (io), T11 I/O136 (io), T12 I/O139 (io), T13 I/O156 (io), T14 I/O166 (io), T15 I/O167 (io), T17 I/O154 (io), T18 I/O155 (io), T19 I/O187 (io), T20 I/O190 (io), U12 I/O140 (io), U13 I/O157 (io), U14 I/O158 (io), U15 I/O150 (io), U16 I/O151 (io), U17 I/O153 (io), U20 I/O188 (io), V12 I/O141 (io), V14 I/O159 (io), V15 I/O144 (io), V16 I/O152 (io), W12 I/O142 (io), W14 I/O160 (io), W15 I/O145 (io), W16 I/O147 (io), Y12 I/O143 (io), Y14 I/O161 (io), Y15 I/O146 (io), Y16 I/O148 (io), Y17 I/O149 (io)
part C pins: A1 GND (power), A2 GND (power), A3 NC, A8 VCC (power), A10 GND (power), A11 GND (power), A13 VCC (power), A18 NC, A19 GND (power), A20 GND (power), B1 GND (power), B2 GND (power), B3 GND (power), B4 NC, B8 VCC (power), B10 GND (power), B11 GND (power), B13 VCC (power), B17 NC, B18 GND (power), B19 GND (power), B20 GND (power), C1 NC, C2 GND (power), C3 GND (power), C4 GND (power), C8 VCC (power), C10 GND (power), C11 GND (power), C13 VCC (power), C17 GND (power), C18 GND (power), C19 GND (power), C20 NC, D2 NC, D3 GND (power), D10 GND (power), D11 GND (power), D18 GND (power), D19 NC, E5 NC, E16 NC, F6 NC, G12 VCC (power), H1 VCC (power), H2 VCC (power), H3 VCC (power), H7 TCK (in), H8 VCC (power), H13 VCC (power), H14 TDI (in), H18 VCC (power), H19 VCC (power), H20 VCC (power), J7 VCC (power), J14 CLK3/IN4 (in), K1 GND (power), K2 GND (power), K3 GND (power), K4 GND (power), K7 CLK0/IN0 (in), K10 GND (power), K11 GND (power), K14 CLK2/IN3 (in), K17 GND (power), K18 GND (power), K19 GND (power), K20 GND (power), L1 GND (power), L2 GND (power), L3 GND (power), L4 GND (power), L7 NC, L10 GND (power), L11 GND (power), L14 IN2 (in), L17 GND (power), L18 GND (power), L19 GND (power), L20 GND (power), M7 CLK1/IN1 (in), M14 VCC (power), N1 VCC (power), N2 VCC (power), N3 VCC (power), N7 TMS (in), N8 VCC (power), N13 VCC (power), N14 TDO (out), N18 VCC (power), N19 VCC (power), N20 VCC (power), P9 VCC (power), R15 NC, T5 NC, T16 NC, U2 NC, U3 GND (power), U10 GND (power), U11 GND (power), U18 GND (power), U19 NC, V1 NC, V2 GND (power), V3 GND (power), V4 GND (power), V8 VCC (power), V10 GND (power), V11 GND (power), V13 VCC (power), V17 GND (power), V18 GND (power), V19 GND (power), V20 NC, W1 GND (power), W2 GND (power), W3 GND (power), W4 NC, W8 VCC (power), W10 GND (power), W11 GND (power), W13 VCC (power), W17 NC, W18 GND (power), W19 GND (power), W20 GND (power), Y1 GND (power), Y2 GND (power), Y3 NC, Y8 VCC (power), Y10 GND (power), Y11 GND (power), Y13 VCC (power), Y18 NC, Y19 GND (power), Y20 GND (power)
